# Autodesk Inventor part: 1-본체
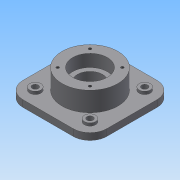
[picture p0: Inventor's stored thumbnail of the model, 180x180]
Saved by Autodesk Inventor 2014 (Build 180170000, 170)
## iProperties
Created: 2015-09
Part Number: 1-본체
Material: Generic
Document SubType Name: Modeling
Designer: study
Density: 1 g/cm^3
Appearance: Default
Author: study
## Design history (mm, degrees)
sketch "스케치1"
  geometry: L1 (-75, 75)-(75, 75); L2 (75, 75)-(75, -75); L3 (75, -75)-(-75, -75); L4 (-75, -75)-(-75, 75); L5 (-75, 75)-(75, -75); L6 (75, 75)-(-75, -75); 1 further point
  constraints: 12 end point, 2 midpoint, 2 parallel, 1 horizontal, 1 perpendicular
  dimensions: "d0" = 150 distance of L1.start L1.end; "d1" = 150 distance of L1.end L2.end
extrude "돌출1" new body sketch "스케치1" distance "d2" = 12; taper "d3" = 0 deg
sketch "스케치2"
  geometry: C1 r 50 at (0, 0); 1 further point
  constraints: 1 centre point, 1 coincident
  dimensions: "d4" = 100 diameter of C1
extrude "돌출2" join sketch "스케치2" distance "d5" = 23; taper "d7" = 0 deg; dims "d6" = 47, "d8" = 0
hole "구멍1" diameter "d11" = 45; stored, may be unused: countersink angle "d15" = 90 deg, drill point angle "d17" = 118 deg; dims "d9" = 10, "d10" = 10, "d12" = 6, "d13" = 62, "d14" = 22, "d16" = 8
hole "구멍2" diameter "d20" = 45; stored, may be unused: countersink angle "d24" = 90 deg, drill point angle "d26" = 118 deg; dims "d18" = 10, "d19" = 10, "d21" = 6, "d22" = 62, "d23" = 22, "d25" = 8
fillet "모깎기1" dims "d27" = 30
sketch "스케치3"
  geometry: L1 (49, -49)-(-49, -49); L2 (-49, -49)-(-49, 49); L3 (-49, 49)-(49, 49); L4 (49, 49)-(49, -49); C1 r 50 at (0, 0) reference; C2 r 10 at (-49, 49); C3 r 10 at (49, 49); C4 r 10 at (-49, -49); C5 r 10 at (49, -49); 2 further points
  constraints: 8 end point, 5 coincident, 4 centre point, 3 equal radius, 1 midpoint, 1 vertical alignment, 9 other
  dimensions: "d28" = 98 distance of L2.end L3.end; "d29" = 20 diameter of C5
extrude "돌출3" join sketch "스케치3" distance "d30" = 5; taper "d31" = 0 deg
sketch "스케치4"
  geometry: C1 r 10 at (0, 0) reference; C2 r 10 at (-98, 0) reference; C3 r 10 at (-98, -98) reference; C4 r 10 at (0, -98) reference; 1 further point
hole "구멍3" sketch "스케치4" at (-98, 0), (0, 0), (0, -98), (-98, -98) diameter "d32" = 11; stored, may be unused: countersink angle "d36" = 90 deg, drill point angle "d38" = 118 deg; dims "d33" = 6, "d34" = 62, "d35" = 22, "d37" = 8
sketch "스케치5"
  geometry: L1 (28.991, -28.991)-(-28.991, -28.991); L2 (-28.991, -28.991)-(-28.991, 28.991); L3 (-28.991, 28.991)-(28.991, 28.991); L4 (28.991, 28.991)-(28.991, -28.991); C1 r 31 at (0, 0) reference; C2 r 50 at (0, 0) reference; 2 further points
  constraints: 8 end point, 1 coincident, 1 midpoint, 1 vertical alignment, 9 other
  dimensions: "d39" = 82 distance of L1.end L3.end
hole "구멍4" sketch "스케치5" at (28.991, 28.991) diameter "d40" = 4.917; stored, may be unused: countersink angle "d44" = 90 deg, drill point angle "d46" = 118 deg; dims "d41" = 10, "d42" = 62, "d43" = 22, "d45" = 13
node "작업 평면1"
node "솔리드1"
pattern_circular "원형 패턴1" dims angle "d48" = 360 deg
mirror "대칭1"
node "투영된 루프1"
node "투영된 루프2"
node "투영된 루프3"
